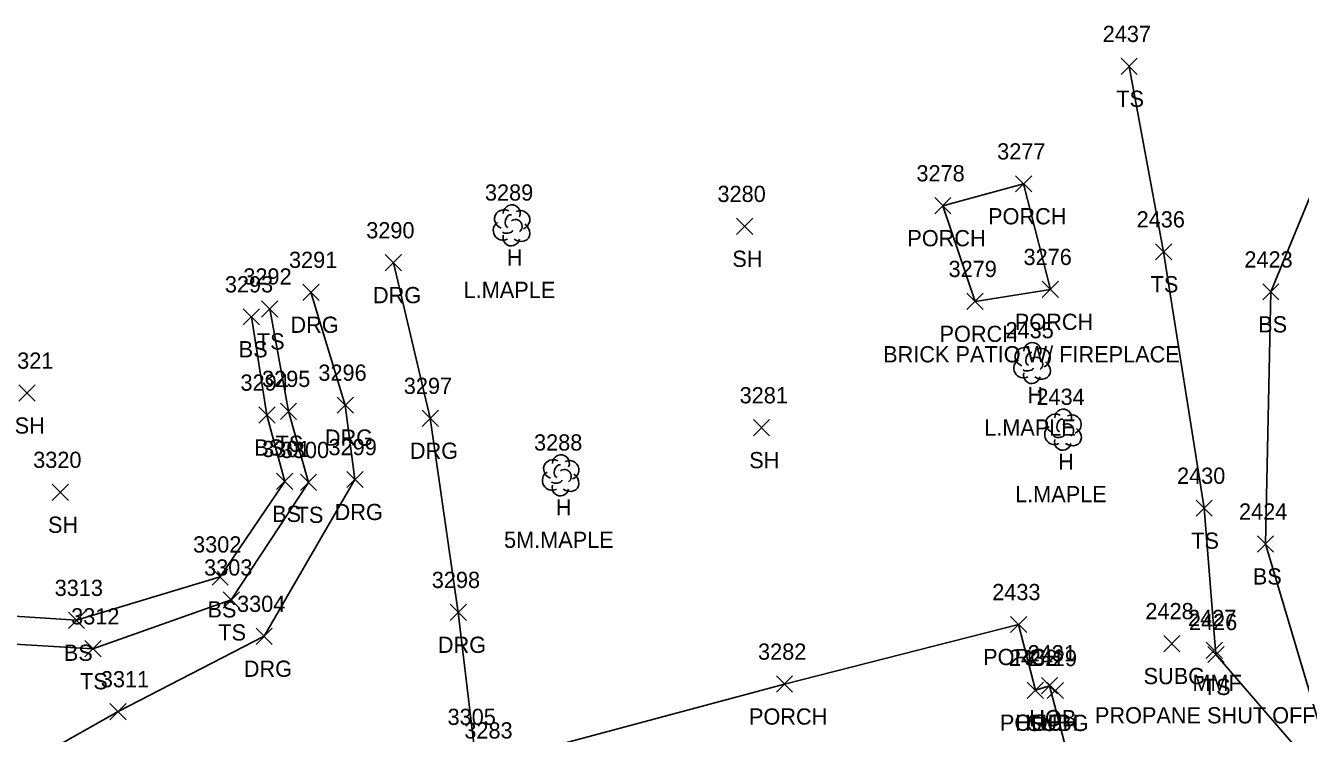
# Model space of a CAD drawing. Extents: x 1520648 to 1523413, y 732854 to 735518.
# Drawn here: x 1521708.9 to 1521866.1, y 733776.2 to 733863.4 of the extents above; entities that cross this region are included whole.
import ezdxf

# ---------------------------------------------------------------- set-up
doc = ezdxf.new("R2010")
doc.units = 0
for name, color, linetype in [('L_A', 7, 'Continuous'), ('L_C', 7, 'Continuous'), ('L_I', 7, 'Continuous'), ('L_TIC', 7, 'Continuous'), ('LBC', 7, 'Continuous'), ('LBF', 7, 'Continuous'), ('LELB', 7, 'Continuous'), ('LTD', 7, 'Continuous'), ('R_A', 7, 'Continuous'), ('R_I', 7, 'Continuous'), ('R_TIC', 7, 'Continuous'), ('RDG', 7, 'Continuous'), ('U_A', 7, 'Continuous'), ('U_I', 7, 'Continuous'), ('U_TIC', 7, 'Continuous')]:
    doc.layers.add(name, color=color, linetype=linetype)

msp = doc.modelspace()

# ---------------------------------------------------------------- linework, layer by layer
at = {"layer": 'L_TIC'}
for points in [[(1521843.96, 733857.39), (1521845.96, 733859.39)], [(1521845.96, 733857.39), (1521843.96, 733859.39)], [(1521830.95, 733842.91), (1521832.95, 733844.91)], [(1521832.95, 733842.91), (1521830.95, 733844.91)], [(1521821, 733840.21), (1521823, 733842.21)], [(1521823, 733840.21), (1521821, 733842.21)], [(1521796.57, 733837.67), (1521798.57, 733839.67)], [(1521798.57, 733837.67), (1521796.57, 733839.67)], [(1521848.2, 733834.53), (1521850.2, 733836.53)], [(1521850.2, 733834.53), (1521848.2, 733836.53)], [(1521834.25, 733829.9), (1521836.25, 733831.9)], [(1521836.25, 733829.9), (1521834.25, 733831.9)], [(1521834.25, 733829.9), (1521836.25, 733831.9)], [(1521836.25, 733829.9), (1521834.25, 733831.9)], [(1521861.42, 733829.59), (1521863.42, 733831.59)], [(1521863.42, 733829.59), (1521861.42, 733831.59)], [(1521824.97, 733828.42), (1521826.97, 733830.42)], [(1521826.97, 733828.42), (1521824.97, 733830.42)], [(1521824.97, 733828.42), (1521826.97, 733830.42)], [(1521826.97, 733828.42), (1521824.97, 733830.42)], [(1521735.77, 733826.52), (1521737.77, 733828.52)], [(1521737.77, 733826.52), (1521735.77, 733828.52)], [(1521738.04, 733827.49), (1521740.04, 733829.49)], [(1521740.04, 733827.49), (1521738.04, 733829.49)], [(1521708.11, 733817.12), (1521710.11, 733819.12)], [(1521710.11, 733817.12), (1521708.11, 733819.12)], [(1521737.69, 733814.41), (1521739.69, 733816.41)], [(1521739.69, 733814.41), (1521737.69, 733816.41)], [(1521740.35, 733814.87), (1521742.35, 733816.87)], [(1521742.35, 733814.87), (1521740.35, 733816.87)], [(1521798.64, 733812.85), (1521800.64, 733814.85)], [(1521800.64, 733812.85), (1521798.64, 733814.85)], [(1521739.88, 733806.23), (1521741.88, 733808.23)], [(1521741.88, 733806.23), (1521739.88, 733808.23)], [(1521742.82, 733806.11), (1521744.82, 733808.11)], [(1521744.82, 733806.11), (1521742.82, 733808.11)], [(1521712.23, 733804.89), (1521714.23, 733806.89)], [(1521714.23, 733804.89), (1521712.23, 733806.89)], [(1521853.2, 733802.93), (1521855.2, 733804.93)], [(1521855.2, 733802.93), (1521853.2, 733804.93)], [(1521860.76, 733798.52), (1521862.76, 733800.52)], [(1521862.76, 733798.52), (1521860.76, 733800.52)], [(1521731.92, 733794.46), (1521733.92, 733796.46)], [(1521733.92, 733794.46), (1521731.92, 733796.46)], [(1521733.29, 733791.62), (1521735.29, 733793.62)], [(1521735.29, 733791.62), (1521733.29, 733793.62)], [(1521714.22, 733789.11), (1521716.22, 733791.11)], [(1521716.22, 733789.11), (1521714.22, 733791.11)], [(1521830.34, 733788.59), (1521832.34, 733790.59)], [(1521832.34, 733788.59), (1521830.34, 733790.59)], [(1521716.25, 733785.6), (1521718.25, 733787.6)], [(1521718.25, 733785.6), (1521716.25, 733787.6)], [(1521854.47, 733785.4), (1521856.47, 733787.4)], [(1521856.47, 733785.4), (1521854.47, 733787.4)], [(1521854.65, 733784.9), (1521856.65, 733786.9)], [(1521856.65, 733784.9), (1521854.65, 733786.9)], [(1521801.48, 733781.25), (1521803.48, 733783.25)], [(1521803.48, 733781.25), (1521801.48, 733783.25)], [(1521834.14, 733781.05), (1521836.14, 733783.05)], [(1521836.14, 733781.05), (1521834.14, 733783.05)], [(1521834.14, 733781.05), (1521836.14, 733783.05)], [(1521836.14, 733781.05), (1521834.14, 733783.05)], [(1521832.4, 733780.49), (1521834.4, 733782.49)], [(1521834.4, 733780.49), (1521832.4, 733782.49)], [(1521832.4, 733780.49), (1521834.4, 733782.49)], [(1521834.4, 733780.49), (1521832.4, 733782.49)]]:
    msp.add_lwpolyline(points, dxfattribs=at)
at = {"layer": 'LBC'}
for points in [[(1521835.14, 733782.05), (1521843.88, 733748.85), (1521828.18, 733744.72), (1521821.83, 733742.98), (1521820.48, 733742.72), (1521819.45, 733746.72)], [(1521835.14, 733782.05), (1521833.4, 733781.49)]]:
    msp.add_lwpolyline(points, dxfattribs=at)
at = {"layer": 'LBF'}
for points in [[(1521835.25, 733830.9), (1521831.95, 733843.91), (1521822, 733841.21), (1521825.97, 733829.42)], [(1521835.25, 733830.9), (1521825.97, 733829.42)], [(1521833.4, 733781.49), (1521831.34, 733789.59), (1521802.48, 733782.25), (1521766.28, 733772.54), (1521766.36, 733771.11), (1521767.8, 733766.66), (1521775.14, 733740), (1521776.12, 733736.39), (1521776.46, 733734.77), (1521819.45, 733746.72)]]:
    msp.add_lwpolyline(points, dxfattribs=at)
at = {"layer": 'LELB'}
for points in [[(1521882.77, 733859.99), (1521870.29, 733849.74), (1521862.42, 733830.59), (1521861.76, 733799.52), (1521871.16, 733767.89)], [(1521871.16, 733767.89), (1521855.65, 733785.9), (1521854.2, 733803.93), (1521849.2, 733835.53), (1521844.96, 733858.39)], [(1521739.04, 733828.49), (1521741.35, 733815.87), (1521743.82, 733807.11), (1521734.29, 733792.62), (1521717.25, 733786.6), (1521704.82, 733787.32), (1521691.66, 733793.27), (1521686.78, 733812.27)], [(1521736.77, 733827.52), (1521738.69, 733815.41), (1521740.88, 733807.23), (1521732.92, 733795.46), (1521715.22, 733790.11), (1521705.6, 733790.73), (1521694.17, 733796.12), (1521688.83, 733813.45)]]:
    msp.add_lwpolyline(points, dxfattribs=at)
at = {"layer": 'LTD'}
for p, q in [((1521768.82, 733838.84), (1521768.82, 733838.84)), ((1521768.82, 733838.84), (1521768.82, 733838.84)), ((1521832.98, 733821.87), (1521832.98, 733821.87)), ((1521832.98, 733821.87), (1521832.98, 733821.87)), ((1521836.79, 733813.66), (1521836.79, 733813.66)), ((1521836.79, 733813.66), (1521836.79, 733813.66)), ((1521774.87, 733808.03), (1521774.87, 733808.03)), ((1521774.87, 733808.03), (1521774.87, 733808.03))]:
    msp.add_line(p, q, dxfattribs=at)
for centre in [(1521768.87, 733840.28), (1521833.03, 733823.3), (1521836.83, 733815.1), (1521774.92, 733809.46)]:
    msp.add_arc(centre, 1.05, 335.5272, 180.9563, dxfattribs=at)
for centre, major_axis, ratio, start_param, end_param in [((1521768.03, 733839.51), (1.21, -0.51), 0.895232, 1.570796, 4.712389), ((1521768.61, 733839.3), (-0.208, -0.792), 0.645439, 3.141593, 6.283185), ((1521769.32, 733838.68), (-0.5, 0.667), 0.989748, 3.141593, 6.283185), ((1521769.86, 733839.43), (-1.14, -0.48), 0.949671, 1.570796, 4.712389), ((1521767.74, 733838.13), (0.58, -1.04), 0.959034, 3.141593, 6.283185), ((1521768.36, 733838.09), (-0.625, -0.083), 0.423636, 0, 3.141593), ((1521769.82, 733838.01), (-1.09, 0.79), 0.841452, 1.570796, 4.712389), ((1521768.82, 733837.34), (0.26, 1.06), 0.942809, 1.570796, 4.712389), ((1521832.19, 733822.54), (1.21, -0.51), 0.895232, 1.570796, 4.712389), ((1521834.02, 733822.45), (-1.14, -0.48), 0.949671, 1.570796, 4.712389), ((1521831.9, 733821.16), (0.58, -1.04), 0.959034, 3.141593, 6.283185), ((1521832.77, 733822.33), (-0.208, -0.792), 0.645439, 3.141593, 6.283185), ((1521833.48, 733821.7), (-0.5, 0.667), 0.989748, 3.141593, 6.283185), ((1521833.98, 733821.04), (-1.09, 0.79), 0.841452, 1.570796, 4.712389), ((1521832.98, 733820.37), (0.26, 1.06), 0.942809, 1.570796, 4.712389), ((1521832.52, 733821.12), (-0.625, -0.083), 0.423636, 0, 3.141593), ((1521835.99, 733814.33), (1.21, -0.51), 0.895232, 1.570796, 4.712389), ((1521836.58, 733814.12), (-0.208, -0.792), 0.645439, 3.141593, 6.283185), ((1521837.29, 733813.49), (-0.5, 0.667), 0.989748, 3.141593, 6.283185), ((1521837.83, 733814.24), (-1.14, -0.48), 0.949671, 1.570796, 4.712389), ((1521835.7, 733812.95), (0.58, -1.04), 0.959034, 3.141593, 6.283185), ((1521836.33, 733812.91), (-0.625, -0.083), 0.423636, 0, 3.141593), ((1521837.79, 733812.83), (-1.09, 0.79), 0.841452, 1.570796, 4.712389), ((1521836.79, 733812.16), (0.26, 1.06), 0.942809, 1.570796, 4.712389), ((1521774.08, 733808.7), (1.21, -0.51), 0.895232, 1.570796, 4.712389), ((1521775.91, 733808.61), (-1.14, -0.48), 0.949671, 1.570796, 4.712389), ((1521773.79, 733807.32), (0.58, -1.04), 0.959034, 3.141593, 6.283185), ((1521774.66, 733808.49), (-0.208, -0.792), 0.645439, 3.141593, 6.283185), ((1521775.37, 733807.86), (-0.5, 0.667), 0.989748, 3.141593, 6.283185), ((1521775.87, 733807.2), (-1.09, 0.79), 0.841452, 1.570796, 4.712389), ((1521774.87, 733806.53), (0.26, 1.06), 0.942809, 1.570796, 4.712389), ((1521774.41, 733807.28), (-0.625, -0.083), 0.423636, 0, 3.141593)]:
    msp.add_ellipse(centre, major_axis=major_axis, ratio=ratio, start_param=start_param, end_param=end_param, dxfattribs=at)
at = {"layer": 'R_TIC'}
for points in [[(1521753.27, 733833.19), (1521755.27, 733835.19)], [(1521755.27, 733833.19), (1521753.27, 733835.19)], [(1521743.11, 733829.54), (1521745.11, 733831.54)], [(1521745.11, 733829.54), (1521743.11, 733831.54)], [(1521747.35, 733815.63), (1521749.35, 733817.63)], [(1521749.35, 733815.63), (1521747.35, 733817.63)], [(1521757.82, 733814.01), (1521759.82, 733816.01)], [(1521759.82, 733814.01), (1521757.82, 733816.01)], [(1521748.54, 733806.46), (1521750.54, 733808.46)], [(1521750.54, 733806.46), (1521748.54, 733808.46)], [(1521761.27, 733790.09), (1521763.27, 733792.09)], [(1521763.27, 733790.09), (1521761.27, 733792.09)], [(1521737.35, 733787.14), (1521739.35, 733789.14)], [(1521739.35, 733787.14), (1521737.35, 733789.14)], [(1521719.34, 733777.85), (1521721.34, 733779.85)], [(1521721.34, 733777.85), (1521719.34, 733779.85)]]:
    msp.add_lwpolyline(points, dxfattribs=at)
at = {"layer": 'RDG'}
for points in [[(1521754.27, 733834.19), (1521758.82, 733815.01), (1521762.27, 733791.09), (1521764.29, 733774.21), (1521748.97, 733769.12), (1521736.37, 733764.01), (1521737.04, 733756.31), (1521741.18, 733735.03), (1521745.34, 733719.41), (1521729.56, 733714.32), (1521720.18, 733709.93), (1521721.48, 733696.01), (1521728.35, 733691.91), (1521736.06, 733688.52)], [(1521744.11, 733830.54), (1521748.35, 733816.63), (1521749.54, 733807.46), (1521738.35, 733788.14), (1521720.34, 733778.85), (1521697.63, 733766.04), (1521693.47, 733757.79), (1521695.59, 733735.07), (1521698.44, 733708.77), (1521699.35, 733693.83), (1521691.81, 733681.75), (1521685.16, 733676.19), (1521682.58, 733672.91)]]:
    msp.add_lwpolyline(points, dxfattribs=at)
at = {"layer": 'U_TIC'}
for points in [[(1521849.22, 733786.24), (1521851.22, 733788.24)], [(1521851.22, 733786.24), (1521849.22, 733788.24)], [(1521834.85, 733780.46), (1521836.85, 733782.46)], [(1521836.85, 733780.46), (1521834.85, 733782.46)]]:
    msp.add_lwpolyline(points, dxfattribs=at)

# ---------------------------------------------------------------- texts
at = {"layer": 'L_A'}
for s, p in [('TS', (1521843.37, 733853.39)), ('PORCH', (1521827.57, 733838.91)), ('PORCH', (1521817.62, 733836.21)), ('H', (1521768.26, 733833.84)), ('SH', (1521796.05, 733833.67)), ('TS', (1521847.61, 733830.53)), ('PORCH', (1521830.87, 733825.9)), ('PORCH', (1521830.87, 733825.9)), ('BS', (1521860.86, 733825.59)), ('TS', (1521737.45, 733823.49)), ('PORCH', (1521821.59, 733824.42)), ('PORCH', (1521821.59, 733824.42)), ('BS', (1521735.21, 733822.52)), ('H', (1521832.42, 733816.87)), ('SH', (1521707.6, 733813.12)), ('TS', (1521739.76, 733810.87)), ('BS', (1521737.13, 733810.41)), ('SH', (1521798.13, 733808.85)), ('H', (1521836.22, 733808.66)), ('H', (1521774.3, 733803.03)), ('BS', (1521739.33, 733802.23)), ('TS', (1521742.23, 733802.11)), ('SH', (1521711.71, 733800.89)), ('TS', (1521852.61, 733798.93)), ('BS', (1521860.2, 733794.52)), ('BS', (1521731.37, 733790.46)), ('TS', (1521732.7, 733787.62)), ('BS', (1521713.66, 733785.11)), ('PORCH', (1521826.96, 733784.59)), ('TS', (1521715.66, 733781.6)), ('MMF', (1521852.76, 733781.4)), ('TS', (1521854.05, 733780.9)), ('PORCH', (1521798.1, 733777.25)), ('PORCH', (1521829.03, 733776.49)), ('HOB', (1521830.91, 733776.49)), ('HOB', (1521832.65, 733777.05)), ('HOB', (1521832.65, 733777.05))]:
    msp.add_text(s, height=2, dxfattribs=at).set_placement(p)
at = {"layer": 'L_C'}
for s, p in [('L.MAPLE', (1521762.93, 733829.84)), ('BRICK PATIO W/ FIREPLACE', (1521814.64, 733821.9)), ('BRICK PATIO W/ FIREPLACE', (1521814.64, 733821.9)), ('L.MAPLE', (1521827.09, 733812.87)), ('L.MAPLE', (1521830.9, 733804.66)), ('5M.MAPLE', (1521767.91, 733799.03)), ('PROPANE SHUT OFF', (1521840.74, 733777.4))]:
    msp.add_text(s, height=2, dxfattribs=at).set_placement(p)
at = {"layer": 'L_I'}
for s, p in [('2437', (1521841.7, 733861.39)), ('3277', (1521828.69, 733846.91)), ('3278', (1521818.74, 733844.21)), ('3289', (1521765.56, 733841.84)), ('3280', (1521794.22, 733841.67)), ('2436', (1521845.88, 733838.53)), ('3276', (1521831.94, 733833.9)), ('3276', (1521831.94, 733833.9)), ('2423', (1521859.16, 733833.59)), ('3292', (1521735.78, 733831.49)), ('3279', (1521822.7, 733832.42)), ('3279', (1521822.7, 733832.42)), ('3293', (1521733.51, 733830.52)), ('2435', (1521829.72, 733824.87)), ('3321', (1521706.42, 733821.12)), ('3294', (1521735.43, 733818.41)), ('3295', (1521738.09, 733818.87)), ('3281', (1521796.95, 733816.85)), ('2434', (1521833.53, 733816.66)), ('3288', (1521771.61, 733811.03)), ('3301', (1521738.11, 733810.23)), ('3300', (1521740.4, 733810.11)), ('3320', (1521709.88, 733808.89)), ('2430', (1521850.86, 733806.93)), ('2424', (1521858.5, 733802.52)), ('3302', (1521729.59, 733798.46)), ('3303', (1521730.95, 733795.62)), ('3313', (1521712.53, 733793.11)), ('2433', (1521828.08, 733792.59)), ('3312', (1521714.56, 733789.6)), ('2427', (1521852.21, 733789.4)), ('2426', (1521852.33, 733788.9)), ('3282', (1521799.22, 733785.25)), ('2432', (1521830.14, 733784.49)), ('2432', (1521830.14, 733784.49)), ('2431', (1521832.45, 733785.05)), ('2431', (1521832.45, 733785.05)), ('3283', (1521763.02, 733775.54))]:
    msp.add_text(s, height=2, dxfattribs=at).set_placement(p)
at = {"layer": 'R_A'}
for p in [(1521751.76, 733829.19), (1521741.59, 733825.54), (1521745.83, 733811.63), (1521756.31, 733810.01), (1521747.03, 733802.46), (1521759.76, 733786.09), (1521735.84, 733783.14)]:
    msp.add_text('DRG', height=2, dxfattribs=at).set_placement(p)
at = {"layer": 'R_I'}
for s, p in [('3290', (1521750.93, 733837.19)), ('3291', (1521741.41, 733833.54)), ('3296', (1521745.03, 733819.63)), ('3297', (1521755.56, 733818.01)), ('3299', (1521746.28, 733810.46)), ('3298', (1521759.01, 733794.09)), ('3304', (1521735.01, 733791.14)), ('3311', (1521718.22, 733781.85)), ('3305', (1521760.95, 733777.21))]:
    msp.add_text(s, height=2, dxfattribs=at).set_placement(p)
at = {"layer": 'U_A'}
for p in [(1521846.74, 733782.24), (1521832.38, 733776.46)]:
    msp.add_text('SUBG', height=2, dxfattribs=at).set_placement(p)
at = {"layer": 'U_I'}
for s, p in [('2428', (1521846.96, 733790.24)), ('2429', (1521832.58, 733784.46))]:
    msp.add_text(s, height=2, dxfattribs=at).set_placement(p)

doc.saveas('drawing.dxf')
